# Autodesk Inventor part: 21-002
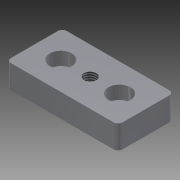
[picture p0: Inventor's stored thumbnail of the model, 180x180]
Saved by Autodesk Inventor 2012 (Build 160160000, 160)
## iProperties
Created: 2004-10
Part Number: 21-002
Material: Steel, High Strength Low Alloy
Document SubType Name: Modeling
Designer: Autodesk, Inc.
Manufacturer: Standard
Standards Organization: Custom
Description: BASE PLATE, 40 SERIES, 40x80, M10
Vendor: PARKER IPS
Catalog Web Link: http://www.parker.com/ead/cm1.asp?cmid=809
Mass: 320.354 g
Surface Area: 105.96 cm^2
Volume: 40.8615 cm^3
Density: 7.84 g/cm^3
CAGE: 1LJX3
Dept. ID: Product Design
Description #2: ---
Finish #1: ---
Finish #2: ---
Material ID: ---
Project Number: ---
Author: Autodesk, Inc.
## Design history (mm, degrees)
sketch "Sketch1"
  geometry: L1 (-38, 19)-(38, 19); L2 (38, 19)-(38, -19); L3 (38, -19)-(-38, -19); L4 (-38, -19)-(-38, 19); 3 further points
  constraints: 8 end point, 2 midpoint, 2 parallel, 1 horizontal, 1 horizontal alignment, 1 perpendicular, 1 vertical alignment
  dimensions: "Dim_A" = 76 distance of L2.end L3.end; "Dim_B" = 38 distance of L1.end L2.end
extrude "Base" new body sketch "Sketch1" taper "d3" = 0 deg; stored distance "Dim_E" = 15.9
sketch "Sketch2"
  geometry: L1 (0, -26.6)-(0, 26.6) reference; L2 (-53.2, 0)-(53.2, 0) reference; 3 further points
  constraints: 1 coincident
  dimensions: "Dim_D1" = 0 distance from line of point (-20, 0) L2; "Dim_D" = 40 diameter of point (-20, 0) L1
hole "MountHole" sketch "Sketch2" diameter "CBoreHoleDia" = 9; stored, may be unused: countersink angle "d10" = 90 deg, drill point angle "d12" = 118 deg; dims "d7" = 6, "d11" = 8, "CBoreDia" = 15, "CBoreDepth" = 9
hole "CenterHole" sketch "Sketch2" diameter "MountHoleDia" = 8.376; stored, may be unused: countersink angle "d17" = 90 deg, drill point angle "d19" = 118 deg; dims "d14" = 6, "d15" = 15, "d16" = 9, "d18" = 8
pattern_linear "Mount Hole Pattern" dims "Dim_B_Pattern_Dist" = 40
fillet "Fillet1" dims "d26" = 3
body "Solid1"
